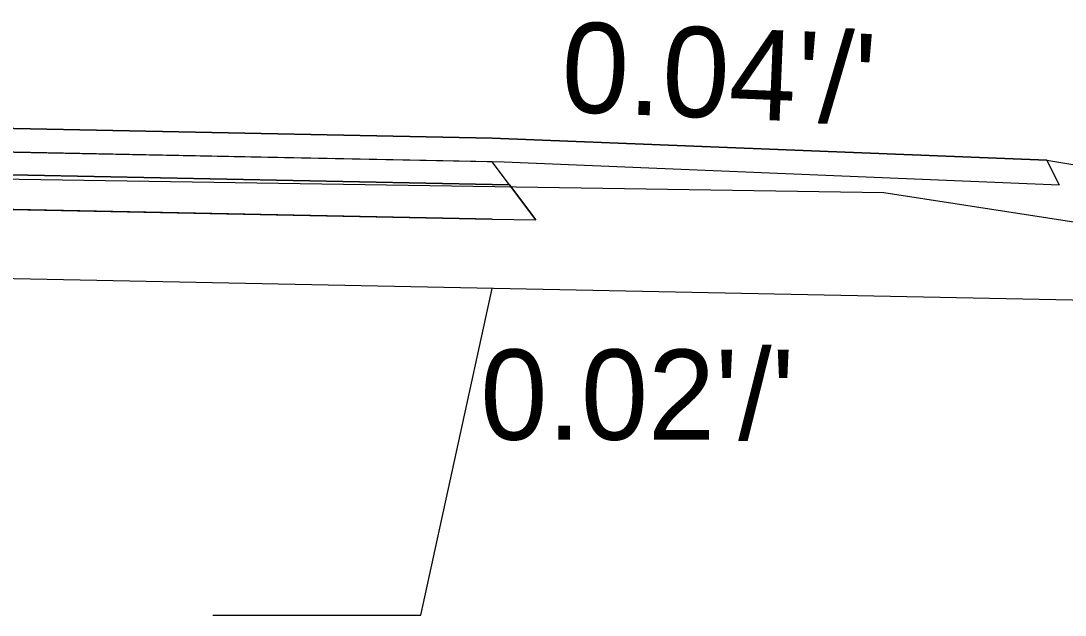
# Model space of a CAD drawing. Extents: x 6848689 to 6848907, y 1900908 to 1901005.
# Drawn here: x 6848753.7 to 6848761.22, y 1900978.64 to 1900982.93 of the extents above; entities that cross this region are included whole.
import ezdxf

# ---------------------------------------------------------------- set-up
doc = ezdxf.new("R2010")
doc.units = 0
doc.layers.add('Default', color=7, linetype='Continuous')
doc.layers.add('R_Draft', color=7, linetype='Continuous')

msp = doc.modelspace()

# ---------------------------------------------------------------- linework, layer by layer
at = {"layer": 'Default'}
for p, q in [((6848746.0972, 1900982.3008), (6848757.095, 1900982.0809)), ((6848757.095, 1900982.0809), (6848746.0972, 1900982.3008)), ((6848746.0972, 1900982.1308), (6848757.1809, 1900981.9091)), ((6848757.095, 1900981.9109), (6848746.0972, 1900982.1308)), ((6848757.095, 1900982.0809), (6848761.0918, 1900981.921)), ((6848761.0918, 1900981.921), (6848757.095, 1900982.0809)), ((6848746.0972, 1900981.9675), (6848757.095, 1900981.7476)), ((6848759.9163, 1900981.6876), (6848746.123, 1900981.9012)), ((6848757.2194, 1900981.7451), (6848757.095, 1900981.9109)), ((6848757.095, 1900981.9109), (6848757.095, 1900981.9109)), ((6848757.1809, 1900981.9091), (6848761.1795, 1900981.7456)), ((6848761.0918, 1900981.921), (6848761.1795, 1900981.7456)), ((6848761.1795, 1900981.7456), (6848761.0918, 1900981.921)), ((6848761.0918, 1900981.921), (6848771.104, 1900980.2525)), ((6848757.095, 1900981.7476), (6848757.2194, 1900981.7451)), ((6848757.4097, 1900981.4913), (6848757.2194, 1900981.7451)), ((6848757.2194, 1900981.7451), (6848757.4097, 1900981.4913)), ((6848757.095, 1900981.4976), (6848746.0972, 1900981.7175)), ((6848765.9191, 1900980.754), (6848759.9163, 1900981.6876)), ((6848757.095, 1900981.4976), (6848757.4097, 1900981.4913)), ((6848767.9338, 1900980.7808), (6848746.0972, 1900981.2175))]:
    msp.add_line(p, q, dxfattribs=at)
for points in [[(6848746.0972, 1900982.1308), (6848757.1809, 1900981.9091), (6848761.1795, 1900981.7456)], [(6848757.2194, 1900981.7451), (6848757.095, 1900981.7476), (6848746.0972, 1900981.9675)], [(6848746.0972, 1900981.9675), (6848757.095, 1900981.7476), (6848757.2194, 1900981.7451)], [(6848746.0972, 1900981.7175), (6848757.095, 1900981.4976), (6848757.4097, 1900981.4913)]]:
    msp.add_lwpolyline(points, dxfattribs=at)
at = {"layer": 'R_Draft'}
for p, q in [((6848756.5814, 1900978.6447), (6848757.095, 1900980.9976)), ((6848755.0814, 1900978.6447), (6848756.5814, 1900978.6447))]:
    msp.add_line(p, q, dxfattribs=at)

# ---------------------------------------------------------------- texts
for s, rotation, p in [("0.04'/'", 357.65738, (6848757.5842, 1900982.2719)), ("0.02'/'", 359.98, (6848757.009, 1900979.9083))]:
    msp.add_text(s, height=0.65, rotation=rotation, dxfattribs=at).set_placement(p)

doc.saveas('drawing.dxf')
